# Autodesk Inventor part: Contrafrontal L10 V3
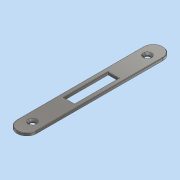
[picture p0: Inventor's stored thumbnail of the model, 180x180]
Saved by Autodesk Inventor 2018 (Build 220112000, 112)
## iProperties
Created: 2020-04
Part Number: Contrafrontal L10 V3
Material: Acero inoxidable
Document SubType Name: Modeling
Designer: PROYECTO
Density: 8 g/cm^3
Appearance: Semipulido
Author: PROYECTO
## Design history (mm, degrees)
sketch "Boceto1"
  geometry: L1 (0, 11.857)-(0, 176.857); L2 (11, 22.857)-(11, 165.857); L3 (-11, 165.857)-(-11, 22.857); L4 (-6, 70.857)-(6, 70.857); L5 (6, 70.857)-(6, 120.857); L6 (6, 120.857)-(-6, 120.857); L7 (-6, 120.857)-(-6, 70.857); L8 (-6, 70.857)-(6, 120.857); L9 (6, 70.857)-(-6, 120.857); C1 r 2.75 at (0, 159.357); C2 r 2.75 at (0, 29.357); A1 r 11 centre (0, 22.857) between (-11, 22.857) and (11, 22.857); A2 r 11 centre (0, 165.857) between (11, 165.857) and (-11, 165.857); 3 further points
  constraints: 20 end point, 6 point on circle, 5 point on line, 4 centre point, 4 tangent, 3 midpoint, 3 parallel, 1 horizontal, 1 perpendicular, 1 vertical
  dimensions: "d0" = 165 distance of L1.start L1.end; "d1" = 22 diameter of A2; "d2" = 5.5 diameter of C1; "d3" = 5.5 diameter of C2; "d4" = 130 distance of C2.centre C1.centre; "d5" = 17.5 distance of L1.start C2.centre; "d6" = 45 distance from line of L6 A2.centre; "d7" = 50 distance of L4.end L5.end; "d8" = 12 distance of L5.end L6.end
extrude "Extrusión1" new body sketch "Boceto1" distance "d9" = 3; taper "d10" = 0 deg
chamfer "Chaflán1" distance "d11" = 2; stored, may be unused: second distance "d12" = 2, angle "d13" = 45 deg
fillet "Empalme1" dims "d14" = 0.5
node "Sólido1"
